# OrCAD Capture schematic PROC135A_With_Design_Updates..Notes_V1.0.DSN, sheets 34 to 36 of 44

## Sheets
34 34. USB1 TYPE-A: size C; title: USB1 TYPE-A
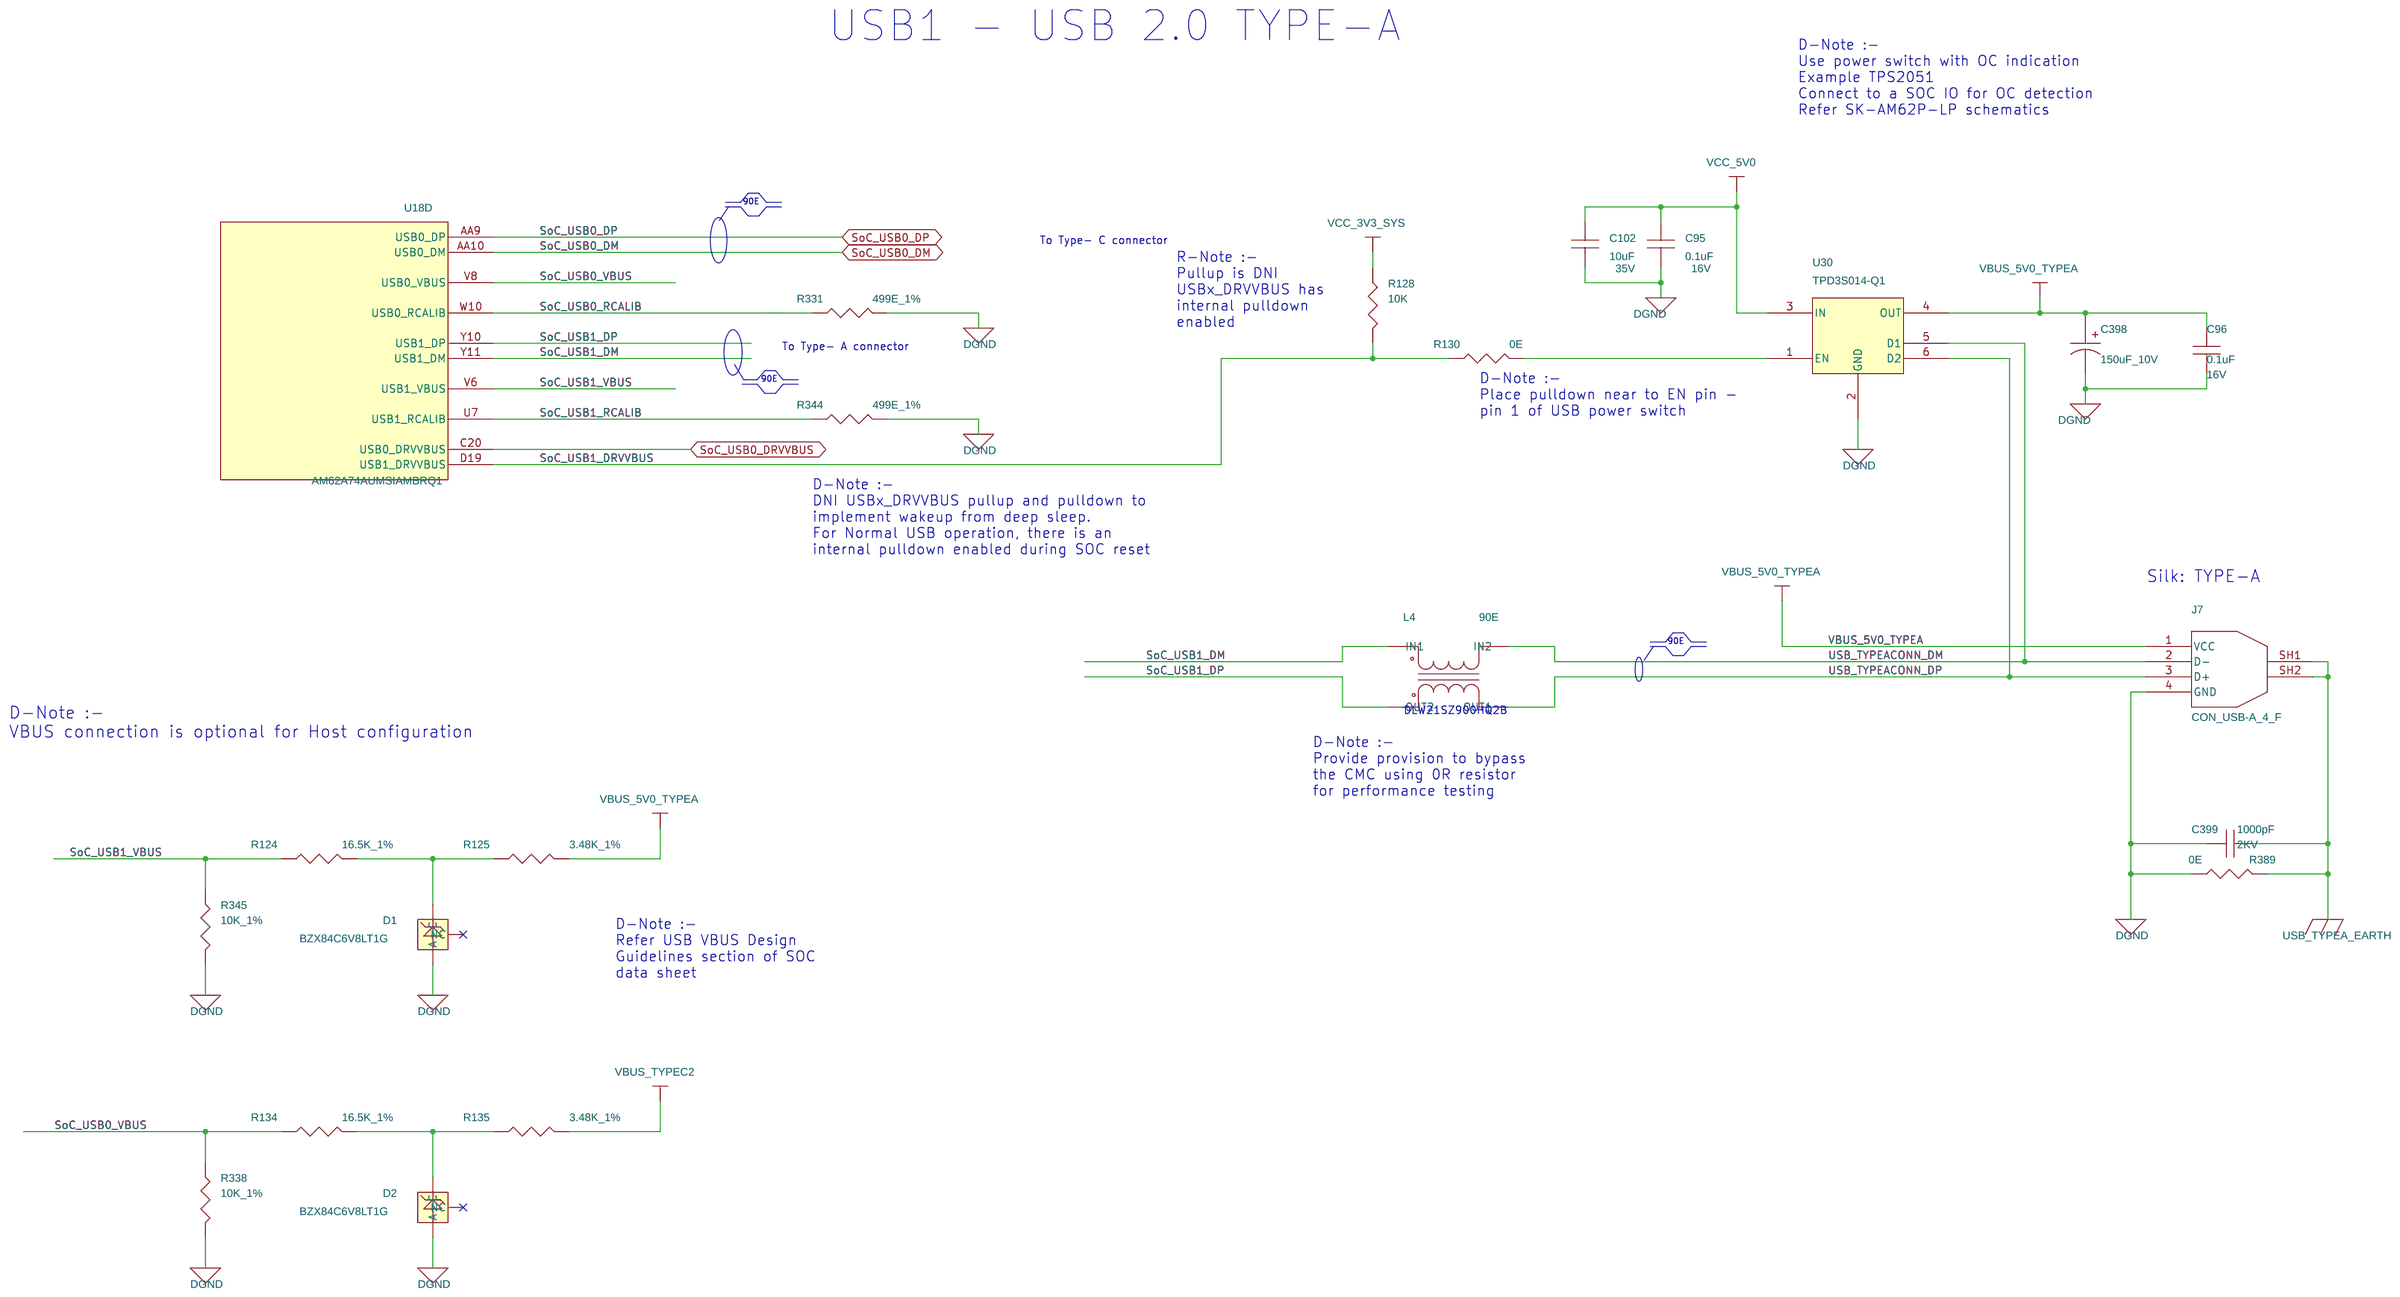
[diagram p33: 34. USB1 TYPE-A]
35 35. USB0 TYPE-C DRP & TEST LED: size C; title: USB0 TYPE-C DRP & USER TEST LED
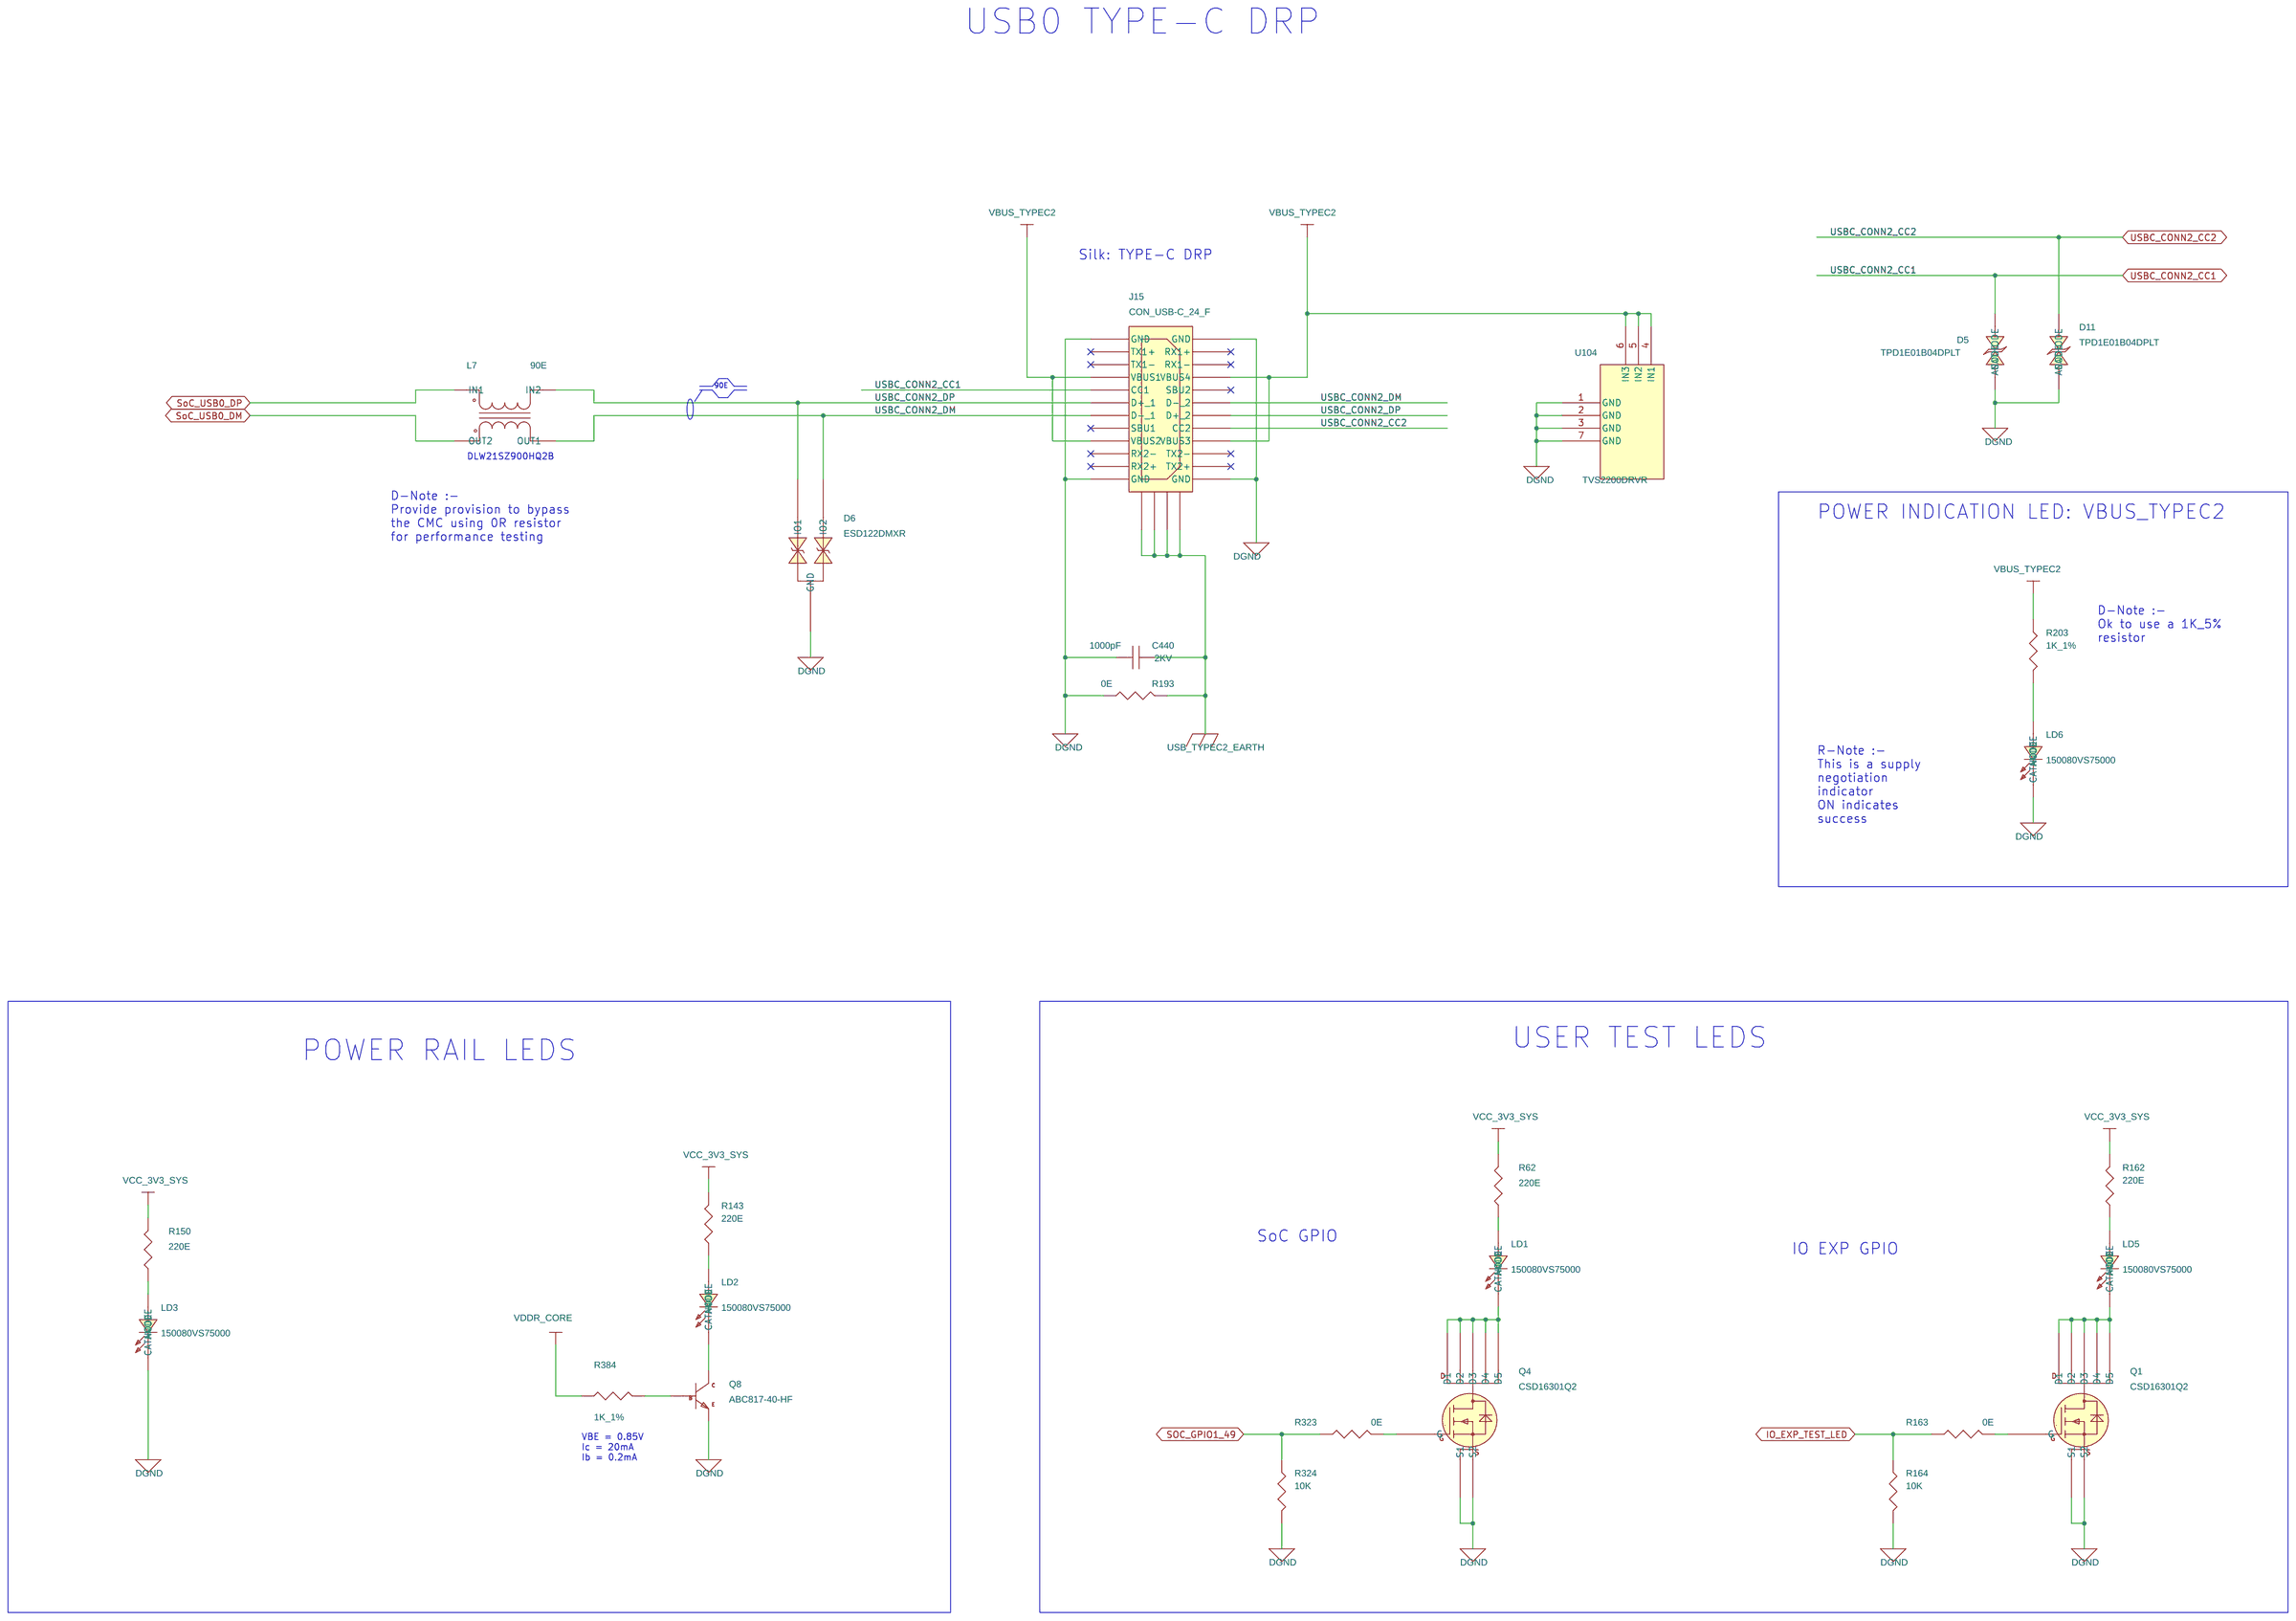
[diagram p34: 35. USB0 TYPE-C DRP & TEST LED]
36 36. SoC UART1 FET SWITCH & BUFF: size C; title: SoC UART1 FET SWITCH & BUFFER
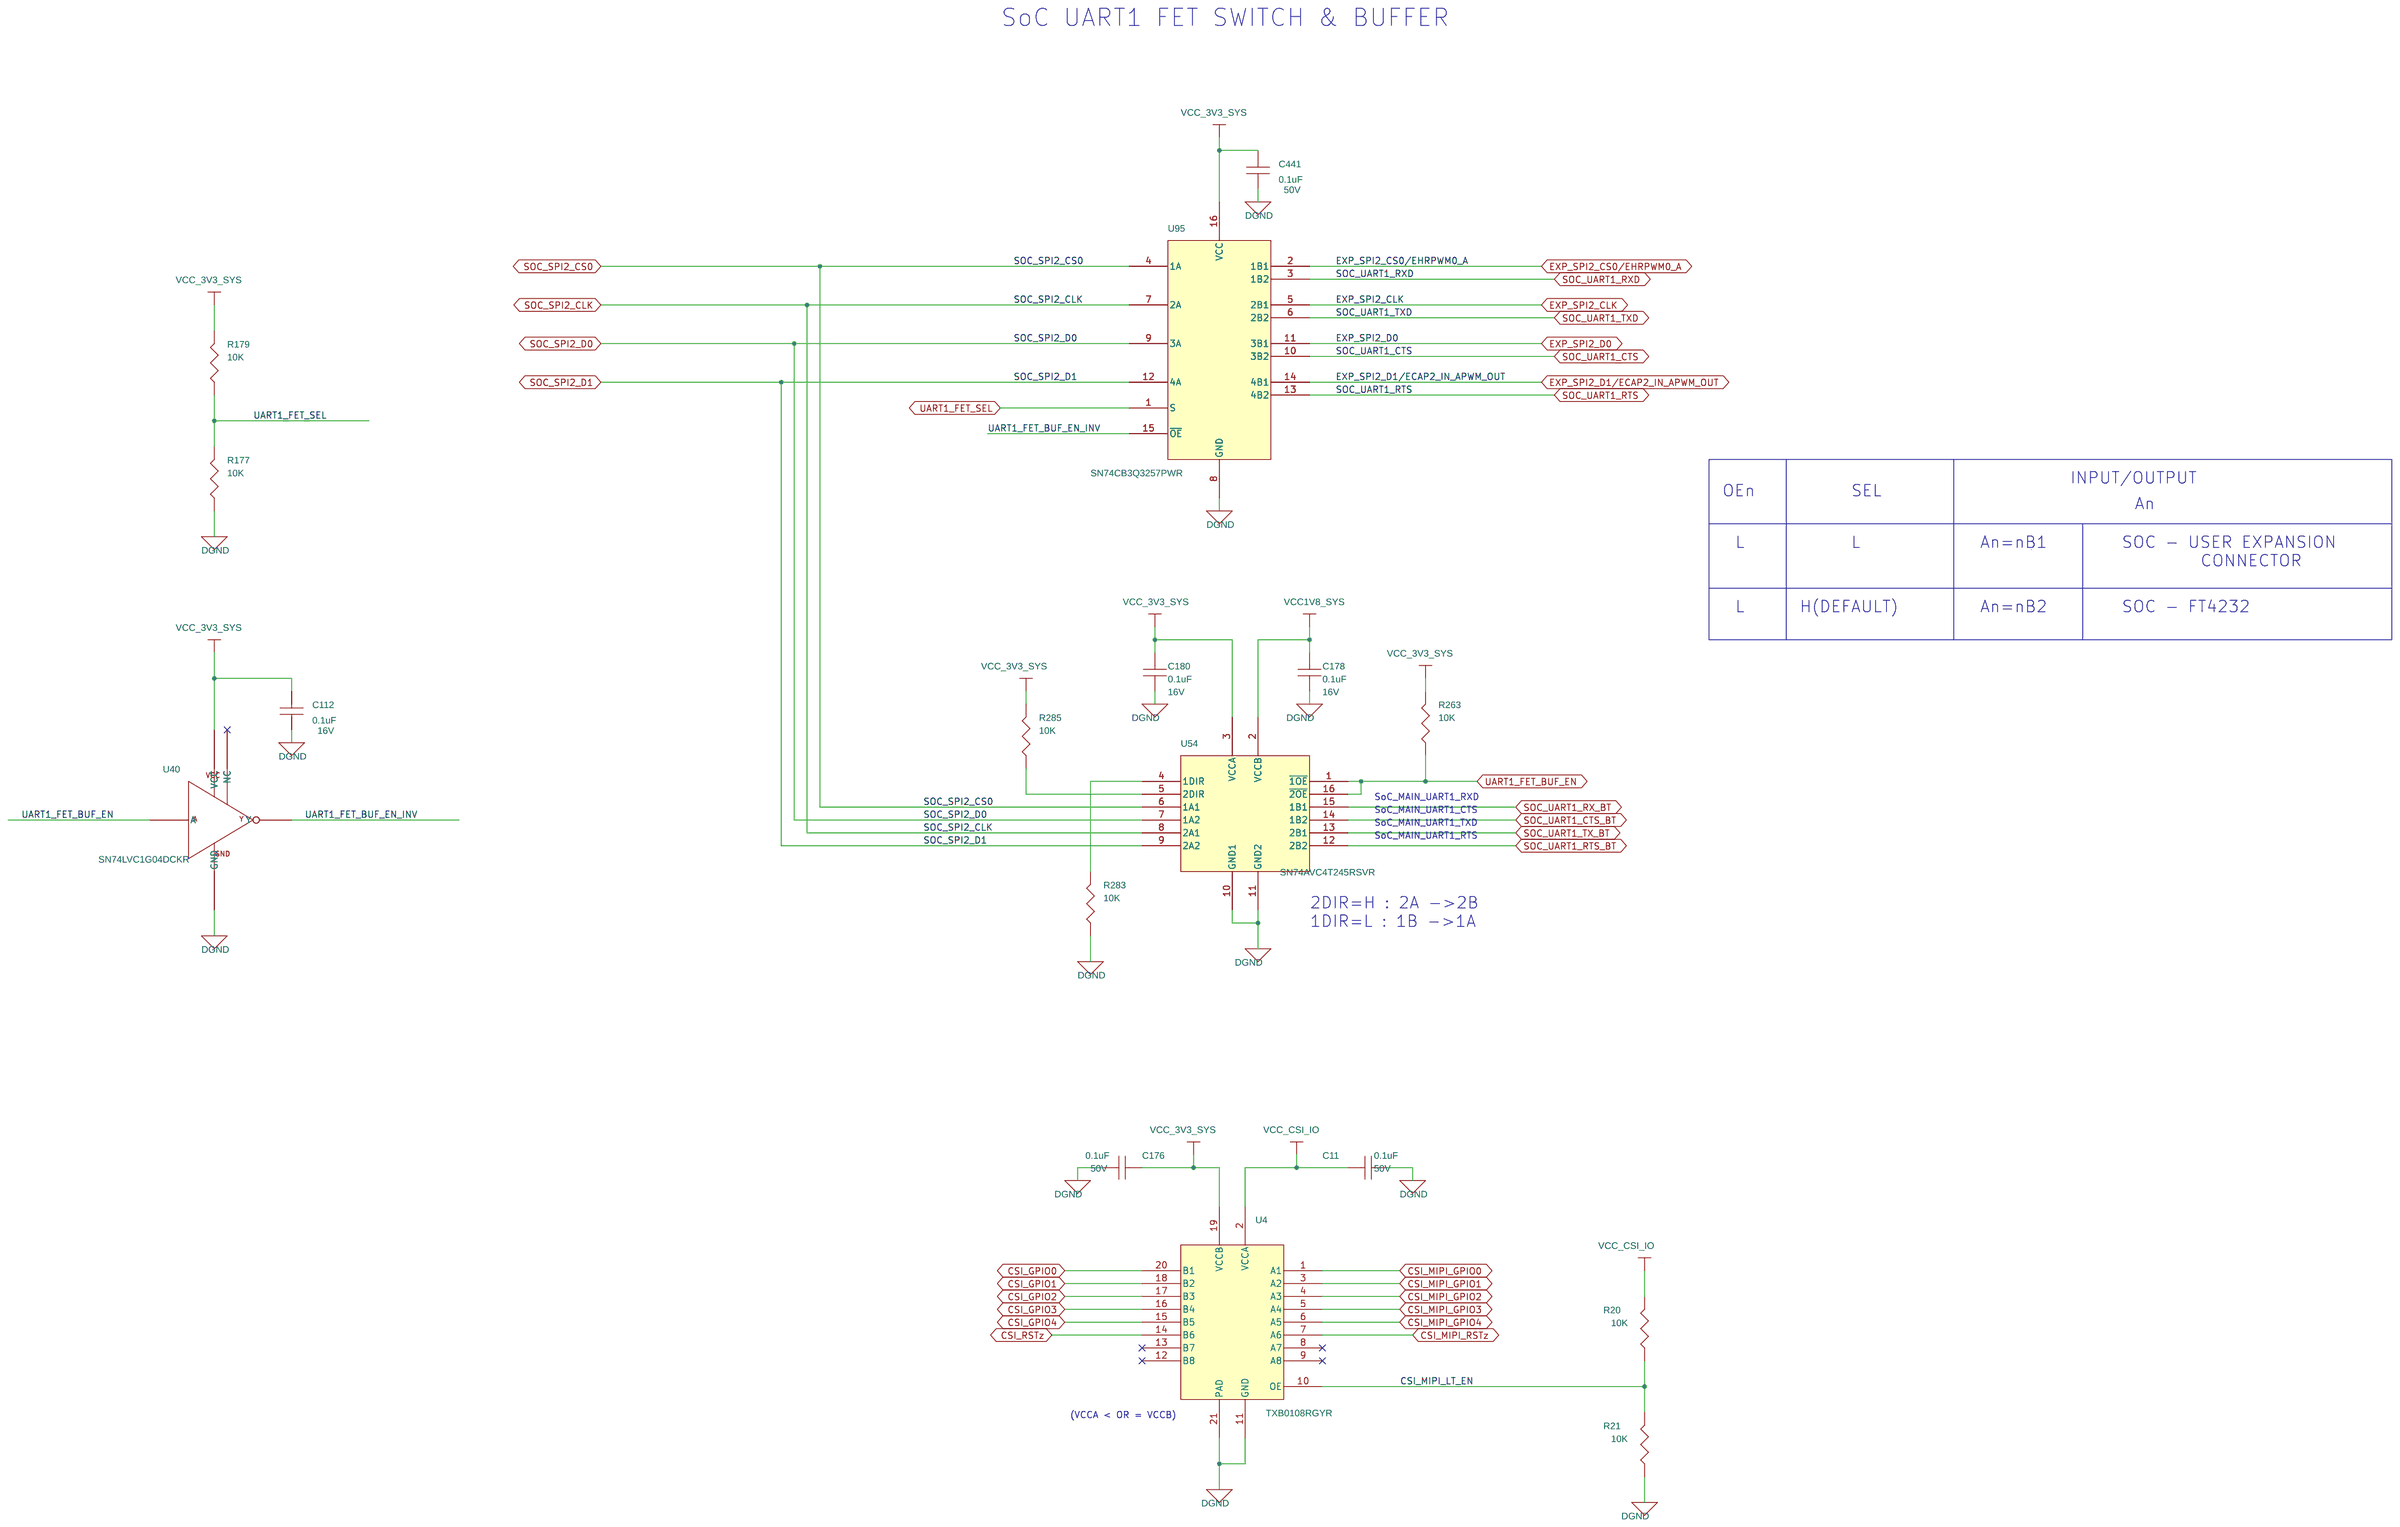
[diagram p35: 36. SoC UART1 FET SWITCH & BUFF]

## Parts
sheet 34. USB1 TYPE-A
C95  0.1uF  [CAP0201_0-5]
C96  0.1uF  [CAP0201_0-5]
C102  10uF  [CAP0603_1]
C398  150uF_10V  [CAPT7343D_3-25]
C399  1000pF  [CAP1206_1-75]
D1  BZX84C6V8LT1G  [SOT23-123_1-2]
D2  BZX84C6V8LT1G  [SOT23-123_1-2]
J7  CON_USB-A_4_F  [CON_USBA4_629104151_S_R_S_7-4]
L4  90E  [IND4_DLW21H_90X60_SMD_1-4]
R124  16.5K_1%  [RES0402_0-5]
R125  3.48K_1%  [RES0201_0-5]
R128  10K  [RES0201_0-5]
R130  0E  [RES0201_0-5]
R134  16.5K_1%  [RES0402_0-5]
R135  3.48K_1%  [RES0201_0-5]
R331  499E_1%  [RES0402_0-5]
R338  10K_1%  [RES0201_0-5]
R344  499E_1%  [RES0402_0-5]
R345  10K_1%  [RES0201_0-5]
R389  0E  [RES0603_0-75]
U30  TPD3S014-Q1  [SOT23-6_1-5]
sheet 35. USB0 TYPE-C DRP & TEST LED
C440  1000pF  [CAP1206_1-75]
D5  TPD1E01B04DPLT  [DIO_DFN0201_0-4]
D6  ESD122DMXR  [X2SON3_ESD122DMX_30X40_0-4]
D11  TPD1E01B04DPLT  [DIO_DFN0201_0-4]
J15  CON_USB-C_24_F  [CON_USBC24_2012670_S_R_S_3-9]
L7  90E  [IND4_DLW21H_90X60_SMD_1-4]
LD1  150080VS75000  [LED_150080VS75000_80X50_SMD_0-8]
LD2  150080VS75000  [LED_150080VS75000_80X50_SMD_0-8]
LD3  150080VS75000  [LED_150080VS75000_80X50_SMD_0-8]
LD5  150080VS75000  [LED_150080VS75000_80X50_SMD_0-8]
LD6  150080VS75000  [LED_150080VS75000_80X50_SMD_0-8]
Q1  CSD16301Q2  [WSON6_CSD13202Q2_80X80_0-8]
Q4  CSD16301Q2  [WSON6_CSD13202Q2_80X80_0-8]
Q8  ABC817-40-HF  [SOT23-123_1-2]
R62  220E  [RES0402_0-5]
R143  220E  [RES0402_0-5]
R150  220E  [RES0402_0-5]
R162  220E  [RES0402_0-5]
R163  0E  [RES0402_0-5]
R164  10K  [RES0201_0-5]
R193  0E  [RES0603_0-75]
R203  1K_1%  [RES0402_0-5]
R323  0E  [RES0402_0-5]
R324  10K  [RES0201_0-5]
R384  1K_1%  [RES0402_0-5]
U104  TVS2200DRVR  [SON6_25-59_85X85_0-8]
sheet 36. SoC UART1 FET SWITCH & BUFF
C11  0.1uF  [CAP0402_0-75]
C112  0.1uF  [CAP0201_0-5]
C176  0.1uF  [CAP0402_0-75]
C178  0.1uF  [CAP0201_0-5]
C180  0.1uF  [CAP0201_0-5]
C441  0.1uF  [CAP0402_0-75]
R20  10K  [RES0201_0-5]
R21  10K  [RES0201_0-5]
R177  10K  [RES0201_0-5]
R179  10K  [RES0201_0-5]
R263  10K  [RES0201_0-5]
R283  10K  [RES0201_0-5]
R285  10K  [RES0201_0-5]
U4  TXB0108RGYR  [QFN20_19-68_185X145_1]
U40  SN74LVC1G04DCKR  [SC70-5]
U54  SN74AVC4T245RSVR  [UQFN16_TMUX1574_70X100_0-6]
U95  SN74CB3Q3257PWR  [TSSOP16_25-59_205X180]
sheet 41. OSCILLATOR
U18  AM62A74AUMSIAMBRQ1  [FBGA484_31-49_710X710_2-7]  (sections A,B,C,D,E,F,G,H,I,J,K,L,M,N,O,P,Q)

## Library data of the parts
C95 C96 = CAP: CAP CERAMIC 0.1uF 16V 10% X5R 0201; Chkd/date: MANIRAJA/230118; Crtd /date: MANIRAJA/230118; Custom_Duty: 15%; Customs_HS_Code: 85322990; Distributor_name: DIGIKEY; Distributor_part_number: 490-14305-1-ND; Footprint Path: Y:\MIS_DATABASE\Library\ALTIUM_TOOL\PCB_FOOTPRINTS\Altium_Footprint_Lib.PcbLib; Height: 0.33MM; Library Path: Y:\MIS_DATABASE\Library\ALTIUM_TOOL\SCHEMATICS_PARTS\MS_DISCRETE_Library.schlib; Mfr_name: MURATA; Mfr_part_number: GRM033R61C104KE14D; Mistral Part No: 120009030072-R; Package: 0201; Part_type: CAPACITORS\CERAMIC; Project: TI_MAXIE_CPB; RoHS: RoHS; Temperature: -55°C+85°C; Tolerance: 10%; Voltage: 16V; Wattage: NA; Weight: 0.33mg; Datasheet: Y:\MIS_DATABASE\DATASHEETS\CAPACITORS\GRM033R61C104KE14.PDF
C102 = CAP: CAP CERAMIC 10uF 35V 20% X5R 0603; Chkd/date: MANIRAJA/170519; Crtd /date: ALVY/160519; Custom_Duty: 15%; Customs_HS_Code: 85322990; Distributor_name: DIGIKEY; Distributor_part_number: 490-13248-1-ND; Footprint Path: Y:\MIS_DATABASE\Library\ALTIUM_TOOL\PCB_FOOTPRINTS\Altium_Footprint_Lib.PcbLib; Height: 1.00MM; Library Path: Y:\MIS_DATABASE\Library\ALTIUM_TOOL\SCHEMATICS_PARTS\MS_DISCRETE_Library.schlib; Mfr_name: MURATA; Mfr_part_number: GRM188R6YA106MA73D; Mistral Part No: 120019050016-R; Package: 0603; Part_type: CAPACITORS\CERAMIC; Project: BRUKER_SD820_COMMONDO; RoHS: RoHS; Temperature: -55°C+85°C; Tolerance: 20%; Voltage: 35V; Wattage: NA; Weight: 9mg; Datasheet: Y:\MIS_DATABASE\DATASHEETS\CAPACITORS\GRM188R6YA106MA73.PDF
C398 = CAP_POL: CAP TANTALUM 150uF 10V 10% ESR 600mE D7343; Chkd/date: ALVY/200921; Crtd /date: MANIRAJA/200921; Custom_Duty: 15%; Customs_HS_Code: 85322990; Distributor_name: DIGIKEY; Distributor_part_number: 718-1960-1-ND; Footprint Path: Y:\MIS_DATABASE\Library\ALTIUM_TOOL\PCB_FOOTPRINTS\Altium_Footprint_Lib.PcbLib; Height: 3.10MM; Library Path: Y:\MIS_DATABASE\Library\ALTIUM_TOOL\SCHEMATICS_PARTS\MS_DISCRETE_Library.schlib; Mfr_name: VISHAY; Mfr_part_number: 293D157X9010D2TE3; Mistral Part No: 120021090007-R; Package: D7343; Part_type: CAPACITORS\TANTALUM; Project: TI_AM62x SKEVM_BRD; RoHS: RoHS; Temperature: -55°C+125°C; Tolerance: 10%; Voltage: 10V; Wattage: NA; Weight: 400mg; Datasheet: Y:\MIS_DATABASE\DATASHEETS\CAPACITORS\293D_SER_MAR20.PDF
C399 C440 = CAP: CAP CERAMIC 1000pF 2KV 10% X7R 1206; Chkd/date: SHREESHAIL/291106; Crtd /date: MAZHAR/281106; Custom_Duty: 15%; Customs_HS_Code: 85322990; Distributor_name: DIGIKEY; Distributor_part_number: 478-2956-1-ND; Footprint Path: Y:\MIS_DATABASE\Library\ALTIUM_TOOL\PCB_FOOTPRINTS\Altium_Footprint_Lib.PcbLib; Height: 1.52MM; Library Path: Y:\MIS_DATABASE\Library\ALTIUM_TOOL\SCHEMATICS_PARTS\MS_DISCRETE_Library.schlib; Mfr_name: AVX CORPORATION; Mfr_part_number: 1206GC102KAT1A; Mistral Part No: 120015080006-R; Package: 1206; Part_type: CAPACITORS\CERAMIC; Project: ADR1B; RoHS: RoHS; Temperature: -55°C+125°C; Tolerance: 10%; Voltage: 2KV; Wattage: NA; Weight: 16.2mg; Datasheet: Y:\MIS_DATABASE\DATASHEETS\CAPACITORS\AVX_HV-MLC.PDF
D1 D2 = DIODE_ZENER_SOT23_13: DIODE ZENER 250mW 6.8V SOT23-123; Chkd/date: MANIRAJA/031017; Crtd /date: MANIRAJA/031017; Custom_Duty: 15%; Customs_HS_Code: 85412900; Distributor_name: DIGIKEY; Distributor_part_number: BZX84C6V8LT1GOSCT-ND; Height: 1.11MM; Mfr_name: ON SEMICONDUCTOR; Mistral Part No: 130017100002-R; Package: SOT23-123; Part_type: DIODE\ZENER; Project: TI_MAXIE_CPB; RoHS: RoHS; Temperature: -65°C+150°C; Tolerance: NA; Voltage: 6.8V; Wattage: NA; Weight: 8mg; Datasheet: Y:\MIS_DATABASE\DATASHEETS\DISCRETES\DIODES\BZX84XX.PDF
J7 = CON_USB-A_4_2SH: CON USB-A TYPE 4POS FEMALE RT SMD; Chkd/date: MANIRAJA/271017; Crtd /date: MANIRAJA/271017; Custom_Duty: 24%; Customs_HS_Code: 85369090; Distributor_name: DIGIKEY; Distributor_part_number: 732-5969-1-ND; Height: 7.35MM; Manufacturer: WURTH ELECTRONICS; Mfr_name: WURTH ELECTRONICS; Mfr_part_number: 629104151021; Mistral Part No: 150017100042-R; Package: SMD; Part_type: CONNECTOR\USB; Project: TI_SVB_MAXWELL_SPM; RoHS: RoHS; Temperature: -40°C+85°C; Tolerance: NA; Voltage: NA; Wattage: NA; Weight: NA; Datasheet: Y:\MIS_DATABASE\DATASHEETS\CONNECTORS\629104151021.PDF
L4 L7 = INDUCTOR_DLW31S: IND COMMON MODE CHOKE 90E 280mA SMD; Chkd/date: MANIRAJA/270619; Crtd /date: MANIRAJA/270619; Custom_Duty: 24%; Customs_HS_Code: 85437099; Distributor_name: NA; Distributor_part_number: NA; Footprint Path: Y:\MIS_DATABASE\Library\ALTIUM_TOOL\PCB_FOOTPRINTS\Altium_Footprint_Lib.PcbLib; Height: 1.40MM; Library Path: Y:\MIS_DATABASE\Library\ALTIUM_TOOL\SCHEMATICS_PARTS\MS_DISCRETE_Library.schlib; Mfr_name: MURATA; Mfr_part_number: DLW21SZ900HQ2B; Mistral Part No: 130019060035-R; Package: SMD; Part_type: INDUCTOR; Project: TI_J7ES_CP; RoHS: RoHS; Temperature: -40°C+105°C; Tolerance: NA; Voltage: NA; Wattage: NA; Weight: 11mg; Datasheet: Y:\MIS_DATABASE\DATASHEETS\DISCRETES\INDUCTORS\DLW21SZ900HQ2B.PDF
R124 R134 = RESISTOR: RES 16.5K 1/16W 1% 0402; Chkd/date: ALVY/091220; Crtd /date: MANIRAJA/091220; Custom_Duty: 15%; Customs_HS_Code: 85332119; Distributor_name: DIGIKEY; Distributor_part_number: YAG3002CT-ND; Footprint Path: Y:\MIS_DATABASE\Library\ALTIUM_TOOL\PCB_FOOTPRINTS\Altium_Footprint_Lib.PcbLib; Height: 0.40MM; Library Path: Y:\MIS_DATABASE\Library\ALTIUM_TOOL\SCHEMATICS_PARTS\MS_DISCRETE_Library.schlib; Mfr_name: YAGEO AMERICA; Mfr_part_number: RC0402FR-0716K5L; Mistral Part No: 110020120011-R; Package: 0402; Part_type: RESISTORS\FIXED; Project: TI_AM243x LP EVM; RoHS: RoHS; Temperature: -55°C+155°C; Tolerance: 1%; Voltage: NA; Wattage: 1/16W; Weight: 0.65mg; Datasheet: Y:\MIS_DATABASE\DATASHEETS\RESISTORS\RCXXXXL-SER_MAR18.PDF
R125 R135 = RESISTOR: RES 3.48K 1/20W 1% 0201; Chkd/date: PRADEEP/281123; Crtd /date: TAMILARASU/071123; Custom_Duty: 15%; Customs_HS_Code: 85322990; Distributor_name: DIGIKEY; Distributor_part_number: P122951CT-ND; Footprint Path: Y:\MIS_DATABASE\Library\ALTIUM_TOOL\PCB_FOOTPRINTS\Altium_Footprint_Lib.PcbLib; Height: 0.26MM; Library Path: Y:\MIS_DATABASE\Library\ALTIUM_TOOL\SCHEMATICS_PARTS\MS_DISCRETE_Library.schlib; Mfr_name: PANASONIC-ECG; Mfr_part_number: ERJ-1GNF3481C; Mistral Part No: 110023110006-R; Package: 0201; Part_type: RESISTORS\FIXED; Project: AM62P SK; RoHS: RoHS; Temperature: -55°C+125°C; Tolerance: 0.01; Voltage: NA; Wattage: 1/20W; Weight: 0.15mg; Datasheet: Y:\MIS_DATABASE\DATASHEETS\RESISTORS\PAN-ERJSER_DEC22.PDF
R20 R21 R128 R164 R177 R179 R263 R283 R285 R324 = RESISTOR: RES 10K 1/20W 5% 0201; Chkd/date: MANIRAJA/050517; Crtd /date: MANIRAJA/050517; Custom_Duty: 15%; Customs_HS_Code: 85332119; Distributor_name: DIGIKEY; Distributor_part_number: 311-10KNCT-ND; Footprint Path: Y:\MIS_DATABASE\Library\ALTIUM_TOOL\PCB_FOOTPRINTS\Altium_Footprint_Lib.PcbLib; Height: 0.26MM; Library Path: Y:\MIS_DATABASE\Library\ALTIUM_TOOL\SCHEMATICS_PARTS\MS_DISCRETE_Library.schlib; Mfr_name: YAGEO AMERICA; Mfr_part_number: RC0201JR-0710KL; Mistral Part No: 110010070051-R; Package: 0201; Part_type: RESISTORS\FIXED; Project: GOLDEN-I LITE; RoHS: RoHS; Temperature: -55°C+125°C; Tolerance: 5%; Voltage: NA; Wattage: 1/20W; Weight: 0.17mg; Datasheet: Y:\MIS_DATABASE\DATASHEETS\RESISTORS\RCXXXXL-SER_MAR18.PDF
R130 = RESISTOR: RES 0E 1/20W 5% 0201; Chkd/date: NAVEED/301214; Crtd /date: MUDDU/120710; Custom_Duty: 15%; Customs_HS_Code: 85332119; Distributor_name: DIGIKEY; Distributor_part_number: 311-0.0NCT-ND; Footprint Path: Y:\MIS_DATABASE\Library\ALTIUM_TOOL\PCB_FOOTPRINTS\Altium_Footprint_Lib.PcbLib; Height: 0.26MM; Library Path: Y:\MIS_DATABASE\Library\ALTIUM_TOOL\SCHEMATICS_PARTS\MS_DISCRETE_Library.schlib; Mfr_name: YAGEO AMERICA; Mfr_part_number: RC0201JR-070RL; Mistral Part No: 110010070067-R; Package: 0201; Part_type: RESISTORS\FIXED; Project: PB_BUGBASE; RoHS: RoHS; Temperature: -55°C+125°C; Tolerance: 5%; Voltage: NA; Wattage: 1/20W; Weight: 0.17mg; Datasheet: Y:\MIS_DATABASE\DATASHEETS\RESISTORS\RCXXXXL-SER_MAR18.PDF
R331 R344 = RESISTOR: RES 499E 1/16W 1% 0402; Chkd/date: MANIRAJA/051020; Crtd /date: ALVY/051020; Custom_Duty: 15%; Customs_HS_Code: 85332119; Distributor_name: DIGIKEY; Distributor_part_number: 311-499LRCT-ND; Footprint Path: Y:\MIS_DATABASE\Library\ALTIUM_TOOL\PCB_FOOTPRINTS\Altium_Footprint_Lib.PcbLib; Height: 0.40MM; Library Path: Y:\MIS_DATABASE\Library\ALTIUM_TOOL\SCHEMATICS_PARTS\MS_DISCRETE_Library.schlib; Mfr_name: YAGEO AMERICA; Mfr_part_number: RC0402FR-07499RL; Mistral Part No: 110020080006-R; Package: 0402; Part_type: RESISTORS\FIXED; Project: AM64XX_EVM; RoHS: RoHS; Temperature: -55°C+155°C; Tolerance: 1%; Voltage: NA; Wattage: 1/16W; Weight: 0.65mg; Datasheet: Y:\MIS_DATABASE\DATASHEETS\RESISTORS\RCXXXXL-SER_MAR18.PDF
R338 R345 = RESISTOR: RES 10K 1/20W 1% 0201; Chkd/date: VASANTHA/270117; Crtd /date: MANIRAJA/270117; Custom_Duty: 15%; Customs_HS_Code: 85332119; Distributor_name: DIGIKEY; Distributor_part_number: 311-10.0KMCT-ND; Footprint Path: Y:\MIS_DATABASE\Library\ALTIUM_TOOL\PCB_FOOTPRINTS\Altium_Footprint_Lib.PcbLib; Height: 0.26MM; Library Path: Y:\MIS_DATABASE\Library\ALTIUM_TOOL\SCHEMATICS_PARTS\MS_DISCRETE_Library.schlib; Mfr_name: YAGEO AMERICA; Mfr_part_number: RC0201FR-0710KL; Mistral Part No: 110011040018-R; Package: 0201; Part_type: RESISTORS\FIXED; Project: GOLDEN-I LITE; RoHS: RoHS; Temperature: -55°C+125°C; Tolerance: 1%; Voltage: NA; Wattage: 1/20W; Weight: 0.17mg; Datasheet: Y:\MIS_DATABASE\DATASHEETS\RESISTORS\RCXXXXL-SER_MAR18.PDF
R193 R389 = RESISTOR: RES 0E 1/10W 5% 0603; Chkd/date: MANIRAJA/051217; Crtd /date: BAVISH/180211; Custom_Duty: 15%; Customs_HS_Code: 85332119; Distributor_name: DIGIKEY; Distributor_part_number: 311-0.0GRCT-ND; Footprint Path: Y:\MIS_DATABASE\Library\ALTIUM_TOOL\PCB_FOOTPRINTS\Altium_Footprint_Lib.PcbLib; Height: 0.55MM; Library Path: Y:\MIS_DATABASE\Library\ALTIUM_TOOL\SCHEMATICS_PARTS\MS_DISCRETE_Library.schlib; Manufacturer: YAGEO AMERICA; Mfr_name: PANASONIC-ECG; Mfr_part_number: RC0603JR-070RL; Mistral Part No: 110011020013-R; Package: 0603; Part_type: RESISTORS\FIXED; Project: KENNEL; RoHS: RoHS; Temperature: -55°C+155°C; Tolerance: 5%; Voltage: NA; Wattage: 1/10W; Weight: 2mg; Datasheet: Y:\MIS_DATABASE\DATASHEETS\RESISTORS\RCXXXXL-SER_MAR18.PDF
U30 = TPD3S014D_SOT23-6: IC ESD PROTECTION FOR AUTO USB PORT WITH CURRENT LIMIT SWITCH SOT23-6; Chkd/date: MANIRAJA/180918; Crtd /date: ALVY/180918; Custom_Duty: 15%; Customs_HS_Code: 85423100; Distributor_name: DIGIKEY; Distributor_part_number: 296-44163-1-ND; Footprint Path: Y:\MIS_DATABASE\Library\ALTIUM_TOOL\PCB_FOOTPRINTS\Altium_Footprint_Lib.PcbLib; Height: 1.45MM; Library Path: Y:\MIS_DATABASE\Library\ALTIUM_TOOL\SCHEMATICS_PARTS\MS_MISCINTERFACE_Library.schlib; Mfr_name: TEXAS INSTRUMENTS; Mfr_part_number: TPD3S014TDBVRQ1; Mistral Part No: 141018090014-R; Package: SOT23-6; Part_type: ICS\INTERFACE; Project: TI_J7ES_EVM_CP; RoHS: RoHS; Temperature: -40°C+105°C; Tolerance: NA; Voltage: NA; Wattage: NA; Weight: NA; Datasheet: Y:\MIS_DATABASE\DATASHEETS\ICS\INTERFACE\TPD3S014-Q1.PDF
D5 D11 = DIODE_TVS_DUAL: DIODE 1CH ESD PROTECTION FOR USB TYPE-C AND THUNDERBOLT3 X2SON2; Chkd/date: MANIRAJA/230920; Crtd /date: ALVY/230920; Custom_Duty: 15%; Customs_HS_Code: 85412900; Distributor_name: DIGIKEY; Distributor_part_number: 296-44484-1-ND; Footprint Path: Y:\MIS_DATABASE\Library\ALTIUM_TOOL\PCB_FOOTPRINTS\Altium_Footprint_Lib.PcbLib; Height: 0.32MM; Library Path: Y:\MIS_DATABASE\Library\ALTIUM_TOOL\SCHEMATICS_PARTS\MS_DISCRETE_Library.schlib; Mfr_name: TEXAS INSTRUMENTS; Mistral Part No: 130020090037-R; Package: X2SON2; Part_type: DIODE\TVS; Project: AM64X_SKEVM; RoHS: RoHS; Temperature: -40°C+125°C; Tolerance: NA; Voltage: NA; Wattage: NA; Weight: 0.2mg; Datasheet: Y:\MIS_DATABASE\DATASHEETS\DISCRETES\DIODES\TPD1E01B04.PDF
D6 = DIODE_ESD122DMXR: DIODE 2-CH ESD PROTECTION FOR USB TYPE-C AND HDMI 2.0 X2SON-3; Chkd/date: MANIRAJA/140817; Crtd /date: MANIRAJA/140817; Custom_Duty: 15%; Customs_HS_Code: 85412900; Distributor_name: DIGIKEY; Distributor_part_number: ESD122DMXR-ND; Height: 0.40MM; Mfr_name: TEXAS INSTRUMENTS; Mistral Part No: 130017080015-R; Package: X2SON-3; Part_type: DIODE\TVS; Project: TI_SVB_CONTROLLER CARD; RoHS: RoHS; Temperature: -40°C+125°C; Tolerance: NA; Voltage: NA; Wattage: NA; Weight: NA; Datasheet: Y:\MIS_DATABASE\DATASHEETS\DISCRETES\DIODES\ESD122XX.PDF
J15 = CON_USB-C_24_1240183621: CON USB-C TYPE 24POS FEMALE RT SMD; Chkd/date: MANIRAJA/050618; Crtd /date: ALVY/040618; Custom_Duty: 24%; Customs_HS_Code: 85369090; Distributor_name: DIGIKEY; Distributor_part_number: WM17992CT-ND; Footprint Path: Y:\MIS_DATABASE\Library\ALTIUM_TOOL\PCB_FOOTPRINTS\Altium_Footprint_Lib.PcbLib; Height: 3.86MM; Library Path: Y:\MIS_DATABASE\Library\ALTIUM_TOOL\SCHEMATICS_PARTS\MS_CONNECTOR_Library.schlib; Mfr_name: MOLEX; Mfr_part_number: 2012670005; Mistral Part No: 150018060002-R; Package: SMD; Part_type: CONNECTOR\USB; Project: TI_J7SVB_USB_ADD-ON-CARD; RoHS: RoHS; Temperature: -40°C+105°C; Tolerance: NA; Voltage: NA; Wattage: NA; Weight: 0.686g; Datasheet: Y:\MIS_DATABASE\DATASHEETS\CONNECTORS\2012670X.PDF
LD1-LD3 LD5 LD6 = DIODE_LED: DIODE LED BRIGHT GREEN SMD; Chkd/date: MANIRAJA/180820; Crtd /date: ALVY/180820; Custom_Duty: 24%; Customs_HS_Code: 85439000; Distributor_name: DIGIKEY; Distributor_part_number: 732-4986-1-ND; Footprint Path: Y:\MIS_DATABASE\Library\ALTIUM_TOOL\PCB_FOOTPRINTS\Altium_Footprint_Lib.PcbLib; Height: 0.80MM; Library Path: Y:\MIS_DATABASE\Library\ALTIUM_TOOL\SCHEMATICS_PARTS\MS_OPTO_Library.schlib; Mfr_name: WURTH ELECTRONICS; Mistral Part No: 130020080012-R; Package: SMD; Part_type: OPTO\LED; Project: AM64x_EVM_BRD; RoHS: RoHS; Temperature: -40°C+85°C; Tolerance: NA; Voltage: NA; Wattage: NA; Weight: 10mg; Datasheet: Y:\MIS_DATABASE\DATASHEETS\DISCRETES\LEDS\150080VS75000.PDF
Q1 Q4 = MOSFET_CSD17313Q2: IC MOSFET N-CHANNEL NEXFET 25V WSON6; Chkd/date: ALVY/071220; Crtd /date: MANIRAJA/071220; Custom_Duty: 15%; Customs_HS_Code: 85423100; Distributor_name: DIGIKEY; Distributor_part_number: 296-25260-1-ND; Footprint Path: Y:\MIS_DATABASE\Library\ALTIUM_TOOL\PCB_FOOTPRINTS\Altium_Footprint_Lib.PcbLib; Height: 0.80MM; Library Path: Y:\MIS_DATABASE\Library\ALTIUM_TOOL\SCHEMATICS_PARTS\MS_MOSFET_Library.schlib; Manufacturer: TEXAS INSTRUMENTS; Mfr_name: TEXAS INSTRUMENTS; Mistral Part No: 142020120008-R; Package: WSON6; Part_type: ICS\POWER\MOSFET; Project: TI_AM243x LP EVM; RoHS: RoHS; Temperature: -55°C+150°C; Tolerance: NA; Voltage: NA; Wattage: NA; Weight: 8.7mg; Datasheet: Y:\MIS_DATABASE\DATASHEETS\ICS\POWER\CSD16301Q2.PDF
Q8 = NPN_123_SOT23-3: TRANSISTOR 45V 500mA NPN GENERAL PURPOSE SOT23-3; Chkd/date: PRAVEEN/260822; Crtd /date: PRAVEEN/260822; Custom_Duty: 15%; Customs_HS_Code: 85423100; Distributor_name: MOUSER; Distributor_part_number: 750-ABC817-40-HF; Footprint Path: Y:\MIS_DATABASE\Library\ALTIUM_TOOL\PCB_FOOTPRINTS\Altium_Footprint_Lib.PcbLib; Height: 1.20MM; Library Path: Y:\MIS_DATABASE\Library\ALTIUM_TOOL\SCHEMATICS_PARTS\MS_MOSFET_Library.schlib; Mfr_name: COMCHIP; Mistral Part No: 142022080040-R; Package: TO-252-3; Part_type: TRANSISTOR\BJT; Project: MS_TI_TMDS64SKEVM; RoHS: RoHS; Temperature: -55°C+150°C; Tolerance: NA; Voltage: 45V; Wattage: NA; Weight: NA; Datasheet: Y:\MIS_DATABASE\DATASHEETS\DISCRETES\TRANSISTORS_FETS\ABC817-40-HF.PDF
R62 R143 R150 R162 = RESISTOR: RES 220E 1/10W 5% 0402; Chkd/date: VASANTHA/291216; Crtd /date: GEETHA/260406; Custom_Duty: 15%; Customs_HS_Code: 85332119; Distributor_name: DIGIKEY; Distributor_part_number: P220JCT-ND; Footprint Path: Y:\MIS_DATABASE\Library\ALTIUM_TOOL\PCB_FOOTPRINTS\Altium_Footprint_Lib.PcbLib; Height: 0.40MM; Library Path: Y:\MIS_DATABASE\Library\ALTIUM_TOOL\SCHEMATICS_PARTS\MS_DISCRETE_Library.schlib; Mfr_name: PANASONIC-ECG; Mfr_part_number: ERJ-2GEJ221X; Mistral Part No: 110009030506-R; Package: 0402; Part_type: RESISTORS\FIXED; Project: RED EYE; RoHS: RoHS; Temperature: -55°C+155°C; Tolerance: 5%; Voltage: NA; Wattage: 1/10W; Weight: 0.8mg; Datasheet: Y:\MIS_DATABASE\DATASHEETS\RESISTORS\PAN-ERJSER_NOV17.PDF
R163 R323 = RESISTOR: RES 0E 1/16W JUMPER 0402; Chkd/date: VASANTHA/201216; Crtd /date: MUDDU/190810; Custom_Duty: 15%; Customs_HS_Code: 85332119; Distributor_name: DIGIKEY; Distributor_part_number: 541-0.0JCT-ND; Footprint Path: Y:\MIS_DATABASE\Library\ALTIUM_TOOL\PCB_FOOTPRINTS\Altium_Footprint_Lib.PcbLib; Height: 0.40MM; Library Path: Y:\MIS_DATABASE\Library\ALTIUM_TOOL\SCHEMATICS_PARTS\MS_DISCRETE_Library.schlib; Mfr_name: VISHAY; Mfr_part_number: CRCW04020000Z0ED; Mistral Part No: 110010080019-R; Package: 0402; Part_type: RESISTORS\FIXED; Project: PB_BUGBASE; RoHS: RoHS; Temperature: -55°C+155°C; Tolerance: NA; Voltage: NA; Wattage: 1/16W; Weight: 0.65mg; Datasheet: Y:\MIS_DATABASE\DATASHEETS\RESISTORS\CRCW0603.PDF
R203 R384 = RESISTOR: RES 1K 1/10W 1% 0402; Chkd/date: VASANTHA/281216; Crtd /date: MAZHAR/150506; Custom_Duty: 15%; Customs_HS_Code: 85332119; Distributor_name: DIGIKEY; Distributor_part_number: P1.00KLCT-ND; Footprint Path: Y:\MIS_DATABASE\Library\ALTIUM_TOOL\PCB_FOOTPRINTS\Altium_Footprint_Lib.PcbLib; Height: 0.40MM; Library Path: Y:\MIS_DATABASE\Library\ALTIUM_TOOL\SCHEMATICS_PARTS\MS_DISCRETE_Library.schlib; Mfr_name: PANASONIC-ECG; Mfr_part_number: ERJ-2RKF1001X; Mistral Part No: 110009030411-R; Package: 0402; Part_type: RESISTORS\FIXED; Project: VOCERA; RoHS: RoHS; Temperature: -55°C+155°C; Tolerance: 1%; Voltage: NA; Wattage: 1/10W; Weight: 0.8mg; Datasheet: Y:\MIS_DATABASE\DATASHEETS\RESISTORS\PAN-ERJSER_NOV17.PDF
U104 = TVS2200_WSON6: IC 22V FLAT-CLAMP SURGE PROTECTION DEVICE WSON6; Chkd/date: MANIRAJA/011021; Crtd /date: ALVY/011021; Custom_Duty: 15%; Customs_HS_Code: 85423100; Distributor_name: DIGIKEY; Distributor_part_number: 296-52187-1-ND; Footprint Path: Y:\MIS_DATABASE\Library\ALTIUM_TOOL\PCB_FOOTPRINTS\Altium_Footprint_Lib.PcbLib; Height: 0.80MM; Library Path: Y:\MIS_DATABASE\Library\ALTIUM_TOOL\SCHEMATICS_PARTS\MS_MISCPOWER_Library.schlib; Mfr_name: TEXAS INSTRUMENTS; Mistral Part No: 142021100001-R; Package: WSON6; Part_type: ICS\POWER; Project: TI_AM62x SKEVM_BRD; RoHS: RoHS; Temperature: -40°C+125°C; Tolerance: NA; Voltage: NA; Wattage: NA; Weight: 12mg; Datasheet: Y:\MIS_DATABASE\DATASHEETS\ICS\POWER\TVS2200.PDF
C11 C176 C441 = CAP: CAP CERAMIC 0.1uF 50V 10% X7R 0402; Alt_Mfr_name: YAGEO AMERICA; Alt_Mfr_part_number: CC0402KRX5R8BB104; Chkd/date: MANIRAJA/261020; Crtd /date: ALVY/211020; Custom_Duty: 15%; Customs_HS_Code: 85322990; Distributor_name: DIGIKEY; Distributor_part_number: 490-10700-1-ND; Footprint Path: Y:\MIS_DATABASE\Library\ALTIUM_TOOL\PCB_FOOTPRINTS\Altium_Footprint_Lib.PcbLib; Height: 0.55MM; Library Path: Y:\MIS_DATABASE\Library\ALTIUM_TOOL\SCHEMATICS_PARTS\MS_DISCRETE_Library.schlib; Mfr_name: MURATA; Mfr_part_number: GRM155R71H104KE14D; Mistral Part No: 120011100014-R; Package: 0402; Part_type: CAPACITORS\CERAMIC; Project: J7_CP; RoHS: RoHS; Temperature: -55°C+125°C; Tolerance: 10%; Voltage: 50V; Wattage: NA; Weight: 3.1mg; Datasheet: Y:\MIS_DATABASE\DATASHEETS\CAPACITORS\GRM155R71H104KE14.PDF
C112 C178 C180 = CAP: CAP CERAMIC 0.1uF 16V 10% X5R 0201; Alt_Mfr_name: YAGEO AMERICA; Alt_Mfr_part_number: CC0402KRX5R8BB104; Chkd/date: MANIRAJA/230118; Crtd /date: MANIRAJA/230118; Custom_Duty: 15%; Customs_HS_Code: 85322990; Distributor_name: DIGIKEY; Distributor_part_number: 490-14305-1-ND; Footprint Path: Y:\MIS_DATABASE\Library\ALTIUM_TOOL\PCB_FOOTPRINTS\Altium_Footprint_Lib.PcbLib; Height: 0.33MM; Library Path: Y:\MIS_DATABASE\Library\ALTIUM_TOOL\SCHEMATICS_PARTS\MS_DISCRETE_Library.schlib; Mfr_name: MURATA; Mfr_part_number: GRM033R61C104KE14D; Mistral Part No: 120009030072-R; Package: 0201; Part_type: CAPACITORS\CERAMIC; Project: TI_MAXIE_CPB; RoHS: RoHS; Temperature: -55°C+85°C; Tolerance: 10%; Voltage: 16V; Wattage: NA; Weight: 0.33mg; Datasheet: Y:\MIS_DATABASE\DATASHEETS\CAPACITORS\GRM033R61C104KE14.PDF
U4 = TXB0108RGYR_VQFN20: IC 8-BIT TRANSLATOR 15KV ESD VQFN20; Chkd/date: VASANTHA/221216; Crtd /date: MUDDU/190510; Custom_Duty: 15%; Customs_HS_Code: 85423100; Distributor_name: DIGIKEY; Distributor_part_number: 296-21528-1-ND; Height: 1.00MM; Mfr_name: TEXAS INSTRUMENTS; Mistral Part No: 141010050005-R; Package: VQFN20; Part_type: ICS\INTERFACE; Project: SHIVA; RoHS: Sb/ Br FREE; Temperature: -40°C+85°C; Tolerance: NA; Voltage: NA; Wattage: NA; Weight: 43mg; Datasheet: Y:\MIS_DATABASE\DATASHEETS\ICS\INTERFACE\TXB0108RGYR.PDF
U40 = SN74LVC1G04DCKR_SC70-5: IC SINGLE INVERTER GATE SC70-5; Chkd/date: SUHAS/221010; Crtd /date: USMAN/150709; Custom_Duty: 15%; Customs_HS_Code: 85423100; Distributor_name: DIGIKEY; Distributor_part_number: 296-11600-1-ND; Height: 1.10MM; Mfr_name: TEXAS INSTRUMENTS; Mistral Part No: 141009070007-R; Part_type: ICS\DIGITAL\GATES; Project: BUG_BASE-II; RoHS: Sb/ Br FREE; Temperature: -40°C+85°C; Datasheet: Y:\MIS_DATABASE\DATASHEETS\ICS\DIGITAL\GATES\SN74LVC1G04-1.PDF
U54 = SN74AVC4T245RSV_UQFN16: IC 2-BIT BUS TRANSCEIVER WITH CONFIGURABLE VOLTAGE TRANSLATION AND 3 STATE O/P UQFN16; Chkd/date: MANIRAJA/040520; Crtd /date: BAVISH/190411; Custom_Duty: 15%; Customs_HS_Code: 85423100; Distributor_name: DIGIKEY; Distributor_part_number: 296-24366-1-ND; Footprint Path: Y:\MIS_DATABASE\Library\ALTIUM_TOOL\PCB_FOOTPRINTS\Altium_Footprint_Lib.PcbLib; Height: 0.55MM; Library Path: Y:\MIS_DATABASE\Library\ALTIUM_TOOL\SCHEMATICS_PARTS\MS_BUSDRIVERTRANSCEIVER_Library.schlib; Mfr_name: TEXAS INSTRUMENTS; Mistral Part No: 141011040011-R; Package: UQFN16; Part_type: ICS\DIGITAL\BUSTRANSCEIVER; Project: HMC; RoHS: RoHS; Temperature: -40°C+85°C; Tolerance: NA; Voltage: NA; Wattage: NA; Weight: 41mg; Datasheet: Y:\MIS_DATABASE\DATASHEETS\ICS\DIGITAL\BUSTRANSCEIVER\SN74AVC4T245-SER.PDF
U95 = SN74CB3Q3257PWR_TSSOP16: IC 4BIT 1-OF-2 FET MULTIPLEXER/DEMULTIPLEXER TSSOP16; Chkd/date: SUHAS/251010; Crtd /date: USMAN/060109; Custom_Duty: 15%; Customs_HS_Code: 85423100; Distributor_name: DIGIKEY; Distributor_part_number: 296-19138-1-ND; Height: 1.20MM; Mfr_name: TEXAS INSTRUMENTS; Mistral Part No: 141009030117-R; Package: TSSOP16; Part_type: ICS\DIGITAL\COMBINATIONAL; Project: OMAP_EVM; RoHS: Sb/ Br FREE; Temperature: -40°C+85°C; Datasheet: Y:\MIS_DATABASE\DATASHEETS\ICS\DIGITAL\COMBINATIONAL\SN74CB3Q3257.PDF
U18 = AM62A-EVM_SOC_FCBGA484: IC AM62A SK EVM SoC MICROPROCESSOR FCBGA484; Chkd/date: PRADEEP/020823; Crtd /date: PRADEEP/020823; Custom_Duty: 15%; Customs_HS_Code: 85423100; Distributor_name: NA; Distributor_part_number: NA; Footprint Path: Y:\MIS_DATABASE\Library\ALTIUM_TOOL\PCB_FOOTPRINTS\Altium_Footprint_Lib.PcbLib; Height: 2.65MM; Library Ref: AM62A-EVM_SoC_FCBGA484; Mfr_name: TEXAS INSTRUMENTS; Mistral Part No: 141230080001-R; Package: FCBGA484; Part_type: ICS\DIGITAL\MICROPROCESSOR; Project: TI_AM62A_SK_EVM; RoHS: NA; Temperature: NA; Tolerance: NA; Voltage: NA; Wattage: NA; Weight: NA; Datasheet: Y:\MIS_DATABASE\DATASHEETS\ICS\DIGITAL\MICROCONTROLLER\AM62A_SK_EVM.PDF

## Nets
DGND: C11.1 C95.2 C96.2 C102.2 C112.1 C176.1 C178.1 C180.1 C398.2 C399.2 C440.2 C441.1 D1.1(A) D2.1(A) D5.2(ANODE) D6.1(GND) D11.2(ANODE) J7.4(GND) J15.A1(GND) J15.A12(GND) J15.B1(GND) J15.B12(GND) LD3.1(CATHODE) LD6.1(CATHODE) Q1.4(S1) Q1.7(S2) Q4.4(S1) Q4.7(S2) Q8.2(EMITTER) R21.1 R164.1 R177.1 R193.2 R283.1 R324.1 R331.2 R338.2 R344.2 R345.2 R389.2 U4.11(GND) U4.21(PAD) U30.2(GND) U40.3(GND) U54.10(GND1) U54.11(GND2) U95.8(GND) U104.1(GND) U104.2(GND) U104.3(GND) U104.7(GND) ; also on sheet 9 10 11 12 13 14 15 16 17 18 19 20 21 22 23 24 25 26 27 28 29 30 31 32 33 37 38 39 40 41 42 43
VBUS_5V0_TYPEA: C96.1 C398.1 J7.1(VCC) R125.2 U30.4(OUT)
VBUS_TYPEC2: J15.A4(VBUS1) J15.A9(VBUS2) J15.B4(VBUS3) J15.B9(VBUS4) R135.2 R203.1 U104.4(IN1) U104.5(IN2) U104.6(IN3) ; also on sheet 9
VCC1V8_SYS: C178.2 U54.2(VCCB) ; also on sheet 12 13 17 18 20 33 38 39 41
VCC_3V3_SYS: C112.2 C176.2 C180.2 C441.2 R62.2 R128.1 R143.2 R150.2 R162.2 R179.2 R263.2 R285.2 U4.19(VCCB) U40.5(VCC) U54.3(VCCA) U95.16(VCC) ; also on sheet 9 10 12 13 17 18 19 21 22 23 25 26 28 29 30 32 33 37 38 39 40 41 42
VCC_5V0: C95.1 C102.1 U30.3(IN) ; also on sheet 9 10 32 37 40
VCC_CSI_IO: C11.2 R20.2 U4.2(VCCA) ; also on sheet 37
VDDR_CORE: R384.1 ; also on sheet 13 14 15
CSI_GPIO0: U4.20(B1) ; also on sheet 37 39
CSI_GPIO1: U4.18(B2) ; also on sheet 37 39
CSI_GPIO2: U4.17(B3) ; also on sheet 41
CSI_GPIO3: U4.16(B4) ; also on sheet 41
CSI_GPIO4: U4.15(B5) ; also on sheet 41
CSI_MIPI_GPIO0: U4.1(A1) ; also on sheet 37
CSI_MIPI_GPIO1: U4.3(A2) ; also on sheet 37
CSI_MIPI_GPIO2: U4.4(A3) ; also on sheet 37
CSI_MIPI_GPIO3: U4.5(A4) ; also on sheet 37
CSI_MIPI_GPIO4: U4.6(A5) ; also on sheet 37
CSI_MIPI_LT_EN: R20.1 R21.2 U4.10(OE)
CSI_MIPI_RSTz: U4.7(A6) ; also on sheet 37
CSI_RSTz: U4.14(B6) ; also on sheet 39
EXP_SPI2_CLK: U95.5(2B1) ; also on sheet 32
EXP_SPI2_CS0/EHRPWM0_A: U95.2(1B1) ; also on sheet 32
EXP_SPI2_D0: U95.11(3B1) ; also on sheet 32
EXP_SPI2_D1/ECAP2_IN_APWM_OUT: U95.14(4B1) ; also on sheet 32
IO_EXP_TEST_LED: R163.1 R164.2 ; also on sheet 39
SOC_GPIO1_49: R323.1 R324.2 ; also on sheet 18
SOC_SPI2_CLK: U54.8(2A1) U95.7(2A) ; also on sheet 32
SOC_SPI2_CS0: U54.6(1A1) U95.4(1A) ; also on sheet 32
SOC_SPI2_D0: U54.7(1A2) U95.9(3A) ; also on sheet 32
SOC_SPI2_D1: U54.9(2A2) U95.12(4A) ; also on sheet 32
SOC_UART1_CTS: U95.10(3B2) ; also on sheet 30
SOC_UART1_CTS_BT: U54.14(1B2) ; also on sheet 17
SOC_UART1_RTS: U95.13(4B2) ; also on sheet 30
SOC_UART1_RTS_BT: U54.12(2B2) ; also on sheet 17
SOC_UART1_RX_BT: U54.15(1B1) ; also on sheet 17
SOC_UART1_RXD: U95.3(1B2) ; also on sheet 30
SOC_UART1_TX_BT: U54.13(2B1) ; also on sheet 17
SOC_UART1_TXD: U95.6(2B2) ; also on sheet 30
SoC_USB0_DM: L7.4(OUT2) U18.AA10(USB0_DM)
SoC_USB0_DP: L7.1(IN1) U18.AA9(USB0_DP)
SoC_USB0_DRVVBUS: U18.C20(USB0_DRVVBUS) ; also on sheet 9
SoC_USB0_RCALIB: R331.1 U18.W10(USB0_RCALIB)
SoC_USB0_VBUS: R134.1 R338.1 U18.V8(USB0_VBUS)
SoC_USB1_DM: L4.1(IN1) U18.Y11(USB1_DM)
SoC_USB1_DP: L4.4(OUT2) U18.Y10(USB1_DP)
SoC_USB1_DRVVBUS: R128.2 R130.1 U18.D19(USB1_DRVVBUS)
SoC_USB1_RCALIB: R344.1 U18.U7(USB1_RCALIB)
SoC_USB1_VBUS: R124.1 R345.1 U18.V6(USB1_VBUS)
UART1_FET_BUF_EN: R263.1 U40.2(A) U54.1(~{1OE}) U54.16(~{2OE}) ; also on sheet 39
UART1_FET_BUF_EN_INV: U40.4(Y) U95.15(~{OE})
UART1_FET_SEL: R177.2 R179.1 U95.1(S) ; also on sheet 39
USB_TYPEA_EARTH: C399.1 J7.SH1 J7.SH2 R389.1
USB_TYPEACONN_DM: J7.2(D-) L4.2(IN2) U30.5(D1)
USB_TYPEACONN_DP: J7.3(D+) L4.3(OUT1) U30.6(D2)
USB_TYPEC2_EARTH: C440.1 J15.SH1 J15.SH2 J15.SH3 J15.SH4 R193.1
USBC_CONN2_CC1: D5.1(CATHODE) J15.A5(CC1) ; also on sheet 9
USBC_CONN2_CC2: D11.1(CATHODE) J15.B5(CC2) ; also on sheet 9
USBC_CONN2_DM: D6.3(IO2) J15.A7(D-_1) J15.B7(D-_2) L7.3(OUT1)
USBC_CONN2_DP: D6.2(IO1) J15.A6(D+_1) J15.B6(D+_2) L7.2(IN2)
N17031262: LD6.2(ANODE) R203.2
N17726648: D2.3(C) R134.2 R135.1
N20199452: D1.3(C) R124.2 R125.1
N20933818: R283.2 U54.4(1DIR)
N20933822: R285.1 U54.5(2DIR)
N21068099: R130.2 U30.1(EN)
N22685157: LD2.1(CATHODE) Q8.3(COLLECTOR)
N22685161: LD2.2(ANODE) R143.1
N22685196: Q8.1(BASE) R384.2
N22685214: LD3.2(ANODE) R150.1
N22685527: LD5.1(CATHODE) Q1.1(D1) Q1.2(D2) Q1.5(D3) Q1.6(D4) Q1.8(D5)
N22685551: LD1.1(CATHODE) Q4.1(D1) Q4.2(D2) Q4.5(D3) Q4.6(D4) Q4.8(D5)
N22685595: Q4.3(G) R323.2
N22685622: LD1.2(ANODE) R62.1
N22685670: Q1.3(G) R163.2
N22685686: LD5.2(ANODE) R162.1

Not connected (* = marked no-connect by the designer): D1 2(NC)*; D2 2(NC)*; J15 A2(TX1+)* A3(TX1-)* A8(SBU1)* A10(RX2-)* A11(RX2+)* B2(TX2+)* B3(TX2-)* B8(SBU2)* B10(RX1-)* B11(RX1+)*; U4 8(A7)* 9(A8)* 12(B8)* 13(B7)*; U40 1(NC)*

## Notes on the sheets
sheet 34
- USB1 - USB 2.0 TYPE-A
- D-Note :-
  Use power switch with OC indication
  Example TPS2051
  Connect to a SOC IO for OC detection
  Refer SK-AM62P-LP schematics
- 90E
- To Type- C connector
- R-Note :-
  Pullup is DNI
  USBx_DRVVBUS has
  internal pulldown
  enabled
- To Type- A connector
- 90E
- D-Note :-
  Place pulldown near to EN pin -
  pin 1 of USB power switch
- D-Note :-
  DNI USBx_DRVVBUS pullup and pulldown to
  implement wakeup from deep sleep.
  For Normal USB operation, there is an
  internal pulldown enabled during SOC reset
- Silk: TYPE-A
- 90E
- D-Note :-
  VBUS connection is optional for Host configuration
- DLW21SZ900HQ2B
- D-Note :-
  Provide provision to bypass
  the CMC using 0R resistor
  for performance testing
- D-Note :-
  Refer USB VBUS Design
  Guidelines section of SOC
  data sheet
sheet 35
- USB0 TYPE-C DRP
- Silk: TYPE-C DRP
- 90E
- DLW21SZ900HQ2B
- D-Note :-
  Provide provision to bypass
  the CMC using 0R resistor
  for performance testing
- POWER INDICATION LED: VBUS_TYPEC2
- D-Note :-
  Ok to use a 1K_5%
  resistor
- R-Note :-
  This is a supply
  negotiation
  indicator
  ON indicates
  success
- USER TEST LEDS
- POWER RAIL LEDS
- SoC GPIO
- IO EXP GPIO
- VBE = 0.85V
  Ic = 20mA
  Ib = 0.2mA
sheet 36
- SoC UART1 FET SWITCH & BUFFER
- OEn
- SEL
- INPUT/OUTPUT
- An
- L
- L
- An=nB1
- SOC - USER EXPANSION
           CONNECTOR
- L
- H(DEFAULT)
- An=nB2
- SOC - FT4232
- SoC_MAIN_UART1_RXD
- SoC_MAIN_UART1_CTS
- SoC_MAIN_UART1_TXD
- SoC_MAIN_UART1_RTS
- 2DIR=H : 2A ->2B
  1DIR=L : 1B ->1A
- (VCCA < OR = VCCB)
